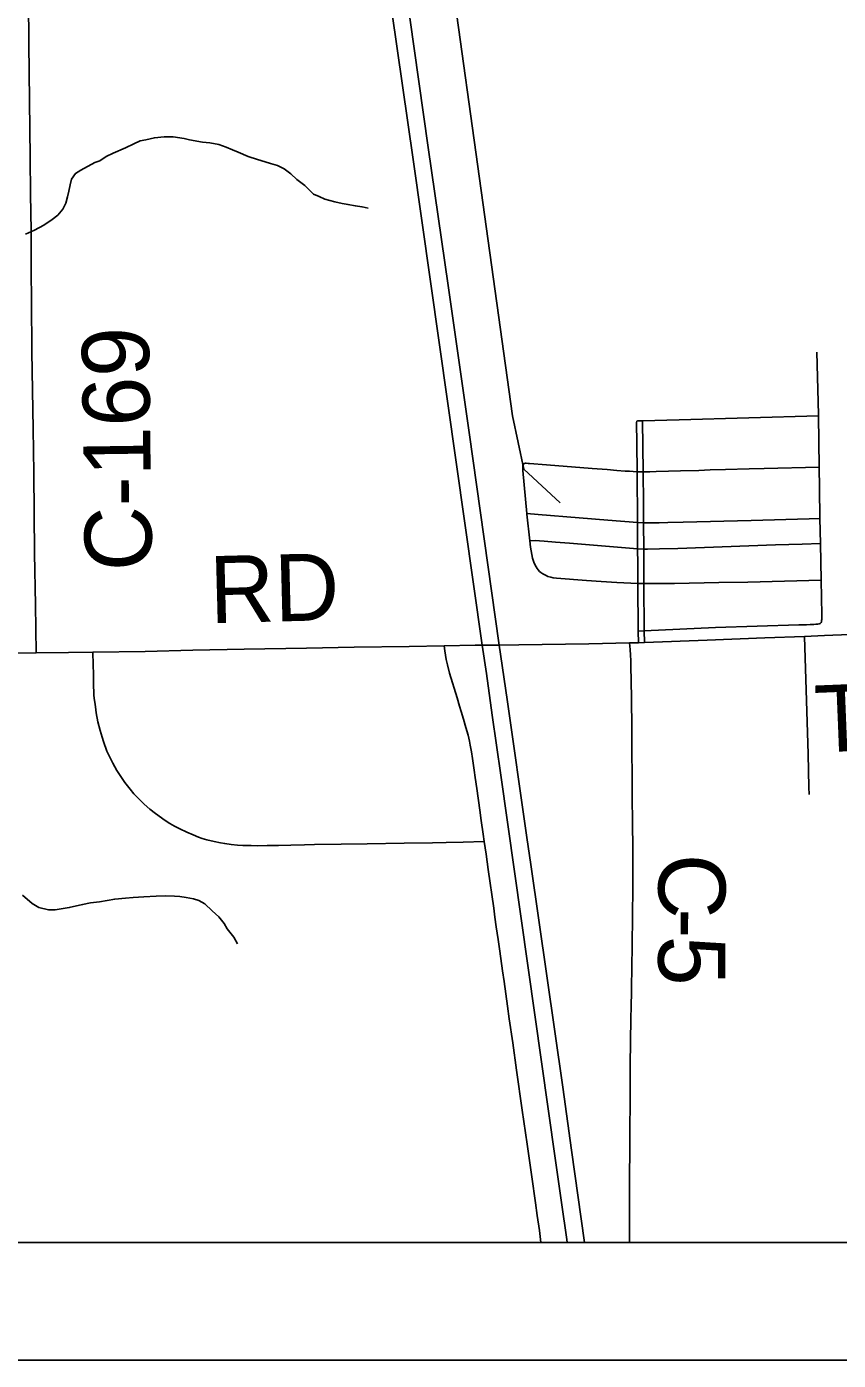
# Model space of a CAD drawing. Extents: x 0 to 34, y -5 to 22.
# Drawn here: x 5.148 to 5.836, y 14 to 15.13 of the extents above; entities that cross this region are included whole.
import ezdxf

# ---------------------------------------------------------------- set-up
doc = ezdxf.new("R2010")
doc.units = 0
for name, color, linetype in [('GM_X_County_Road', 7, 'Continuous'), ('GM_X_County_Road_Text', 7, 'Continuous'), ('GM_X_Minor_River', 7, 'Continuous'), ('GM_X_Rail_Line', 7, 'Continuous'), ('GM_X_State_Route', 7, 'Continuous'), ('GM_X_Township_Road', 7, 'Continuous'), ('GM_X_Township_Road_Text', 7, 'Continuous'), ('GM_X_US_Route', 7, 'Continuous'), ('SH_Cut_Line', 7, 'Continuous'), ('SH_Data', 7, 'Continuous')]:
    doc.layers.add(name, color=color, linetype=linetype)

msp = doc.modelspace()

# ---------------------------------------------------------------- linework, layer by layer
at = {"layer": 'GM_X_County_Road'}
for points in [[(5.1559, 14.5996), (5.1554, 14.6402), (5.1547, 14.6837), (5.154, 14.7521), (5.1535, 14.7894), (5.1525, 14.8547), (5.152, 14.8982), (5.1519, 14.9231), (5.1517, 14.9573), (5.1513, 14.9884), (5.1509, 15.0195), (5.1498, 15.1159), (5.1492, 15.1905), (5.1486, 15.2838), (5.1484, 15.3429), (5.1481, 15.3958), (5.1481, 15.4093)], [(5.2041, 14.6001), (5.2484, 14.6007), (5.2887, 14.6018), (5.3321, 14.6027), (5.3849, 14.6036), (5.4253, 14.6043), (5.4719, 14.6049), (5.5016, 14.6055)], [(5.5016, 14.6055), (5.5278, 14.606), (5.5337, 14.6061)], [(5.5337, 14.6061), (5.5483, 14.6062), (5.565, 14.6064), (5.6241, 14.6073), (5.6586, 14.608)], [(5.6586, 14.1), (5.6586, 14.1086), (5.6587, 14.1406), (5.659, 14.1934), (5.6592, 14.221), (5.6593, 14.2503), (5.6598, 14.2901), (5.6601, 14.2995), (5.6603, 14.313), (5.6607, 14.336), (5.6609, 14.3485), (5.6612, 14.3796), (5.6614, 14.3975), (5.6615, 14.4112), (5.6614, 14.4349), (5.6613, 14.4543), (5.6609, 14.4788), (5.6608, 14.4933), (5.6606, 14.5182), (5.6605, 14.5374), (5.6602, 14.5591), (5.66, 14.5775), (5.6598, 14.5864), (5.6597, 14.5931), (5.6594, 14.5976), (5.6591, 14.6024), (5.6586, 14.608)], [(5.0702, 14.5986), (5.1182, 14.5991), (5.1559, 14.5996)], [(5.1559, 14.5996), (5.1833, 14.5998), (5.2041, 14.6001)]]:
    msp.add_lwpolyline(points, dxfattribs=at)
at = {"layer": 'GM_X_Minor_River'}
for points in [[(5.147, 14.9546), (5.1546, 14.9578), (5.1625, 14.9621), (5.1696, 14.9668), (5.1745, 14.9707), (5.1786, 14.9757), (5.1812, 14.9807), (5.1826, 14.9861), (5.1836, 14.991), (5.1847, 14.9964), (5.1861, 15.001), (5.1894, 15.006), (5.1939, 15.0087), (5.2056, 15.0151), (5.2101, 15.0167), (5.2154, 15.0202), (5.2214, 15.023), (5.2316, 15.0277), (5.2388, 15.0309), (5.2441, 15.0337), (5.249, 15.0345), (5.2562, 15.0362), (5.2646, 15.0371), (5.2722, 15.0369), (5.2813, 15.0355), (5.2859, 15.0345), (5.297, 15.0324), (5.3031, 15.0318), (5.3108, 15.0304), (5.3169, 15.0282), (5.3223, 15.026), (5.3272, 15.0239), (5.3357, 15.0202), (5.3434, 15.0177), (5.3499, 15.0159), (5.3545, 15.0145), (5.3606, 15.0127), (5.366, 15.0098), (5.3718, 15.0057), (5.3768, 15.0008), (5.3837, 14.9956), (5.3911, 14.9885), (5.3957, 14.9863), (5.4007, 14.9842), (5.4091, 14.982), (5.4153, 14.9806), (5.4202, 14.9796), (5.4263, 14.9786), (5.4321, 14.9775), (5.4374, 14.9765)], [(5.1445, 14.3943), (5.1527, 14.3873), (5.1584, 14.3839), (5.1665, 14.3818), (5.1722, 14.3819), (5.184, 14.3837), (5.1953, 14.3862), (5.2021, 14.3878), (5.2097, 14.3887), (5.2226, 14.3909), (5.2318, 14.3918), (5.2382, 14.3923), (5.2473, 14.3929), (5.2576, 14.3935), (5.2652, 14.3936), (5.2732, 14.3934), (5.2778, 14.3931), (5.2831, 14.3924), (5.2892, 14.391), (5.2938, 14.3896), (5.2988, 14.387), (5.305, 14.381), (5.3109, 14.3758), (5.3152, 14.3702), (5.3179, 14.3657), (5.3234, 14.3586), (5.3265, 14.3529)]]:
    msp.add_lwpolyline(points, dxfattribs=at)
at = {"layer": 'GM_X_Rail_Line'}
msp.add_lwpolyline([(4.2939, 16.5478), (4.428, 16.1111), (4.4985, 16.0565), (5.0896, 15.6072), (5.1407, 15.5965), (5.3829, 15.5608), (5.4458, 15.537), (5.4636, 15.5061), (5.4813, 15.3635), (5.5596, 14.8004), (5.5691, 14.7552), (5.5999, 14.7267)], dxfattribs=at)
at = {"layer": 'GM_X_State_Route'}
msp.add_line((5.5483, 14.6062), (5.5227, 14.7863), dxfattribs=at)
for points in [[(5.5227, 14.7863), (5.505, 14.9109), (5.4881, 15.0278), (5.4646, 15.194), (5.4387, 15.3749), (5.4335, 15.4116), (5.4292, 15.4408), (5.4161, 15.531), (5.3973, 15.6649), (5.36, 15.9296), (5.3304, 16.1389), (5.3252, 16.1853), (5.3231, 16.2079), (5.3208, 16.238), (5.3196, 16.2589), (5.3187, 16.2815), (5.3145, 16.3995), (5.3117, 16.4694), (5.3107, 16.5035), (5.3105, 16.5288), (5.3103, 16.5523), (5.3103, 16.5583)], [(5.6059, 14.1), (5.6056, 14.1025), (5.601, 14.1339), (5.5958, 14.1714), (5.5496, 14.4959), (5.5422, 14.5468), (5.5374, 14.582), (5.5337, 14.6061), (5.4753, 15.0177), (5.4303, 15.3315), (5.4238, 15.3782), (5.4165, 15.43), (5.3932, 15.5931), (5.367, 15.7778), (5.3228, 16.0887), (5.3139, 16.1564), (5.3088, 16.2059), (5.3057, 16.2493), (5.3034, 16.3051), (5.3002, 16.3921), (5.2969, 16.4884), (5.2964, 16.5144)], [(5.575, 14.4202), (5.5718, 14.4431), (5.5549, 14.56), (5.5483, 14.6062)], [(5.6204, 14.1), (5.6094, 14.1782), (5.6021, 14.2316), (5.575, 14.4202)]]:
    msp.add_lwpolyline(points, dxfattribs=at)
at = {"layer": 'GM_X_Township_Road'}
msp.add_line((5.6586, 14.608), (5.6662, 14.6082), dxfattribs=at)
for points in [[(5.821, 14.6254), (5.8213, 14.626), (5.8214, 14.627), (5.8215, 14.6278), (5.8215, 14.6317), (5.8209, 14.6612), (5.8203, 14.6924), (5.82, 14.7136), (5.8195, 14.7391), (5.8192, 14.757), (5.8186, 14.8005), (5.8186, 14.8015), (5.8173, 14.8545)], [(5.6649, 14.7961), (5.6656, 14.7963), (5.6675, 14.7964), (5.6697, 14.7964), (5.7008, 14.797), (5.8186, 14.8005)], [(5.6713, 14.6084), (5.6712, 14.6183), (5.6709, 14.6584), (5.6708, 14.6876), (5.6706, 14.7099), (5.6705, 14.7264), (5.6703, 14.753), (5.6697, 14.7964)], [(5.6662, 14.6082), (5.6661, 14.6181), (5.6656, 14.6585), (5.6656, 14.6751), (5.6654, 14.6877), (5.6654, 14.6905), (5.6655, 14.706), (5.6655, 14.7102), (5.665, 14.7531), (5.6648, 14.7771), (5.6646, 14.7948), (5.6649, 14.7961)], [(5.5691, 14.7597), (5.5686, 14.7592), (5.5684, 14.7584), (5.5682, 14.7568), (5.5682, 14.7556), (5.5683, 14.7542), (5.5716, 14.7177), (5.5717, 14.7171), (5.5742, 14.6947), (5.5748, 14.6892), (5.5766, 14.68), (5.5771, 14.6782), (5.5777, 14.6766), (5.5788, 14.674), (5.5804, 14.6711), (5.5814, 14.6699), (5.5825, 14.6686), (5.5836, 14.6677), (5.5851, 14.6666), (5.588, 14.6651), (5.5896, 14.6644), (5.5919, 14.6637), (5.5941, 14.6633), (5.5968, 14.663), (5.6221, 14.6609), (5.6345, 14.6602), (5.648, 14.6593), (5.6598, 14.6587), (5.6656, 14.6585), (5.6709, 14.6584), (5.6782, 14.6584), (5.6888, 14.6584), (5.6967, 14.6585), (5.7342, 14.6592), (5.7588, 14.6596), (5.8209, 14.6612)], [(5.5691, 14.7597), (5.5698, 14.7601), (5.5705, 14.7603), (5.5712, 14.7603), (5.5728, 14.7602), (5.5739, 14.7602), (5.5882, 14.7591), (5.627, 14.756), (5.6397, 14.755), (5.6478, 14.7543), (5.6549, 14.7537), (5.6586, 14.7535), (5.6617, 14.7533), (5.665, 14.7531), (5.6683, 14.753), (5.6703, 14.753), (5.6758, 14.7531), (5.6813, 14.7533), (5.6916, 14.7535), (5.7018, 14.7539), (5.7175, 14.7543), (5.727, 14.7546), (5.7399, 14.755), (5.76, 14.7555), (5.7726, 14.7558), (5.8192, 14.757)], [(5.5716, 14.7177), (5.5813, 14.7169), (5.6161, 14.7141), (5.6402, 14.7122), (5.6655, 14.7102), (5.6706, 14.7099), (5.6839, 14.7099), (5.6911, 14.7101), (5.7042, 14.7103), (5.7618, 14.7118), (5.8107, 14.7133), (5.82, 14.7136)], [(5.5742, 14.6947), (5.5787, 14.6948), (5.5825, 14.6946), (5.5864, 14.6943), (5.596, 14.6935), (5.6077, 14.6925), (5.6654, 14.6877), (5.6708, 14.6876), (5.674, 14.6875), (5.6841, 14.6878), (5.6995, 14.6881), (5.7822, 14.6911), (5.8048, 14.6918), (5.8203, 14.6924)], [(5.6661, 14.6181), (5.6712, 14.6183), (5.7314, 14.6212), (5.8022, 14.6233), (5.8087, 14.6235), (5.8118, 14.6236), (5.8149, 14.6237), (5.8165, 14.6238), (5.8176, 14.6239), (5.8183, 14.624), (5.8192, 14.6242), (5.8201, 14.6246), (5.821, 14.6254)], [(5.807, 14.6136), (5.8237, 14.6143), (5.8737, 14.6163), (5.9541, 14.6198), (5.9628, 14.6201)], [(5.5356, 14.4397), (5.5347, 14.4459), (5.5331, 14.4575), (5.5319, 14.4662), (5.5293, 14.4846), (5.528, 14.494), (5.5271, 14.5003), (5.5257, 14.5101), (5.5248, 14.5156), (5.5238, 14.5213), (5.523, 14.5247), (5.5219, 14.5298), (5.5201, 14.5363), (5.518, 14.5434), (5.5161, 14.5498), (5.5147, 14.5545), (5.5126, 14.5615), (5.5063, 14.5823), (5.5044, 14.5894), (5.5034, 14.5939), (5.5027, 14.5976), (5.5021, 14.6014), (5.5016, 14.6055)], [(5.6662, 14.6082), (5.6713, 14.6084), (5.7243, 14.6103), (5.7733, 14.6123), (5.807, 14.6136)], [(5.8107, 14.4795), (5.8106, 14.4857), (5.8099, 14.5138), (5.807, 14.6136)], [(5.2041, 14.6001), (5.2044, 14.5894), (5.2047, 14.5815), (5.2047, 14.576), (5.2047, 14.5709), (5.2048, 14.5672), (5.205, 14.564), (5.2053, 14.561), (5.2057, 14.5578), (5.2062, 14.5538), (5.207, 14.5488), (5.2084, 14.5412), (5.2102, 14.5338), (5.2119, 14.5282), (5.2131, 14.5245), (5.216, 14.5162), (5.2186, 14.5107), (5.221, 14.5062), (5.2244, 14.4999), (5.2312, 14.4897), (5.2356, 14.4842), (5.2389, 14.4801), (5.2435, 14.4752), (5.2475, 14.4713), (5.2524, 14.4671), (5.257, 14.4634), (5.2652, 14.4574), (5.2692, 14.4549), (5.2732, 14.4528), (5.2778, 14.4504), (5.2836, 14.4476), (5.289, 14.4453), (5.2936, 14.4435), (5.2967, 14.4423), (5.3006, 14.4412), (5.3069, 14.4397), (5.3123, 14.4385), (5.3158, 14.4379), (5.3212, 14.4372), (5.3266, 14.4367), (5.331, 14.4364), (5.3381, 14.4362), (5.3432, 14.4361), (5.3518, 14.4362), (5.3613, 14.4363), (5.3718, 14.4366), (5.3833, 14.4369), (5.3919, 14.4371), (5.4143, 14.4375), (5.4364, 14.4377), (5.4678, 14.4382), (5.4917, 14.4386), (5.5033, 14.4388), (5.5178, 14.4391), (5.5356, 14.4397)], [(5.5836, 14.1), (5.5823, 14.1101), (5.5805, 14.1228), (5.579, 14.1336), (5.5759, 14.1555), (5.5719, 14.1833), (5.5678, 14.212), (5.563, 14.2458), (5.5597, 14.2692), (5.5568, 14.2893), (5.5553, 14.3001), (5.5524, 14.3211), (5.5511, 14.3301), (5.5488, 14.3467), (5.5474, 14.3566), (5.5458, 14.3675), (5.5447, 14.3756), (5.5436, 14.3831), (5.539, 14.4159), (5.5371, 14.4291), (5.5356, 14.4397)]]:
    msp.add_lwpolyline(points, dxfattribs=at)
at = {"layer": 'GM_X_US_Route'}
msp.add_lwpolyline([(2.1, 16.5221), (2.1, 14.1), (6.156, 14.1)], dxfattribs=at)
at = {"layer": 'SH_Cut_Line'}
msp.add_lwpolyline([(2.1, 16.5221), (2.1, 14.1), (6.156, 14.1)], dxfattribs=at)
at = {"layer": 'SH_Data'}
for p, q in [((2.1, 14.1), (8.9, 14.1)), ((2, 14), (9, 14))]:
    msp.add_line(p, q, dxfattribs=at)

# ---------------------------------------------------------------- texts
at = {"layer": 'GM_X_County_Road_Text'}
for s, height, rotation, p in [('C-169', 0.05682, 90.8198, (5.2543, 14.6693)), ('RD', 0.05682, 1.4743, (5.3036, 14.6247)), ('C', 0.0568, 270.0722, (5.6831, 14.4292)), ('-', 0.0568, 269.8668, (5.6832, 14.383)), ('5', 0.0568, 269.7524, (5.6831, 14.3599))]:
    msp.add_text(s, height=height, rotation=rotation, dxfattribs=at).set_placement(p)
at = {"layer": 'GM_X_Township_Road_Text'}
msp.add_text('T', height=0.0568, rotation=2.3002, dxfattribs=at).set_placement((5.8165, 14.5151))

doc.saveas('drawing.dxf')
